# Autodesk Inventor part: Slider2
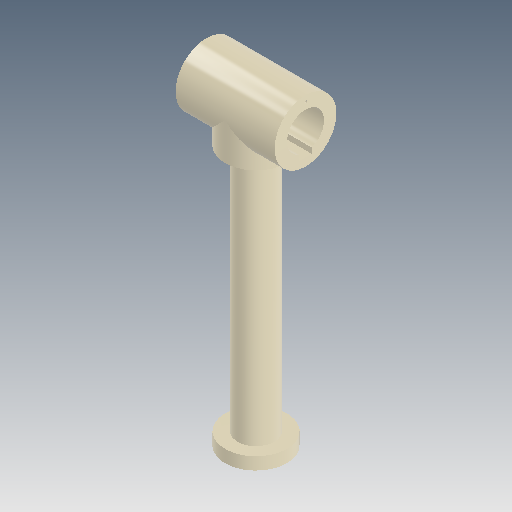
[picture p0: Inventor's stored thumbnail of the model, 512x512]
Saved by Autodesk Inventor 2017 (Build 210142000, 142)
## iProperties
Created: 2015-03
Part Number: Slider2
Document SubType Name: Modeling
Designer: Administrator
Density: 1 g/cm^3
Mass: 2.19166 g
Surface Area: 19.3417 cm^2
Volume: 2.19166 cm^3
Material: Generic
Appearance: Light Beige
Author: Administrator
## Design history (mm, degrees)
sketch "Sketch1"
  geometry: L1 (-4.037, 0)-(-4.037, 3); L2 (-4.037, 3)-(-20.037, 3); L3 (-59.037, 0)-(-4.037, 0); L4 (-20.037, 3)-(-20.037, 5); L5 (-20.037, 5)-(-4.037, 5); L6 (-4.037, 5)-(-4.037, 3); L7 (0, 0)-(-4.037, 0)
  constraints: 14 end point, 4 perpendicular, 2 parallel, 1 vertical, 1 other
  dimensions: "d0" = 3 distance of L1.start L1.end; "d3" = 16 distance of L1.end L2.end; "d5" = 2 distance between parallel lines of L5 L2
revolve "Revolution2" sketch "Sketch1" stored, may be unused: angle "d6" = 90 deg
sketch "Sketch2"
  geometry: L1 (-20.037, -5)-(-20.037, 5) reference; L2 (-4.037, -5)-(-4.037, 5) reference; L3 (-20.037, 0)-(-4.037, 0); L4 (-12.037, 0)-(-12.037, -40.229); L5 (-12.037, 0)-(-12.037, -66.218); L6 (-12.037, -3)-(-9.037, -3); L7 (-9.037, -3)-(-9.037, -4); L8 (-9.037, -4)-(-12.037, -4); L9 (-9.037, -4)-(-7.037, -4); L10 (-7.037, -4)-(-7.037, -6); L11 (-7.037, -6)-(-9.051, -6); L12 (-9.051, -6)-(-9.051, -46); L13 (-9.051, -46)-(-7.051, -46); L14 (-7.051, -46)-(-7.051, -48); L15 (-7.051, -48)-(-8.94, -48); L16 (-8.94, -48)-(-12.037, -48); L17 (-12.037, -3)-(-12.037, -48)
  constraints: 30 end point, 6 perpendicular, 5 parallel, 3 midpoint, 3 point on line, 2 collinear
  dimensions: "d7" = 0 distance between parallel lines of L4 L5; "d8" = 3 distance from line of L4.start L6; "d9" = 3 distance between parallel lines of L5 L7; "d10" = 1 distance between parallel lines of L6 L8; "d11" = 2 distance between parallel lines of L9 L11; "d12" = 2 distance from line of L13 L15.end; "d13" = 40 distance between parallel lines of L13 L11; "d14" = 2 distance between parallel lines of L7 L10; "d15" = 2 distance between parallel lines of L12 L14
revolve "Revolution3" sketch "Sketch2" stored, may be unused: angle "d16" = 90 deg
sketch "Sketch3"
  geometry: C1 r 5 at (0, 0) reference; C2 r 0.25 at (0, 4)
  constraints: 1 centre point
  dimensions: "d17" = 0.5 diameter of C2; "d18" = 4 distance of C2.centre C1.centre
extrude "Extrusion1" cut sketch "Sketch3" stored distance "d19" = 10; taper "d20" = 0 deg
sketch "Sketch5"
  geometry: L1 (-4, -3)-(4, -3) reference; L2 (4, 3)-(-4, 3) reference; A1 r 5 centre (0, 0) between (-4, -3) and (4, -3) reference; A2 r 5 centre (0, 0) between (4, 3) and (-4, 3) reference
extrude "Extrusion3" join sketch "Sketch5" stored distance "d23" = 10; taper "d24" = 0 deg
sketch "Sketch6"
  geometry: L1 (1, -3.7)-(-1, -3.7); L2 (-1, -3.7)-(-1, -1.7); L3 (-1, -1.7)-(1, -1.7); L4 (1, -1.7)-(1, -3.7); C1 r 0.25 at (0, 4) reference; C2 r 3 at (0, 0) reference; C3 r 5 at (0, 0) reference; 1 further point
  constraints: 8 end point, 2 parallel, 1 horizontal, 1 perpendicular
  dimensions: "d25" = 2 distance of L2.end L3.end; "d26" = 1 distance from line of L2 C2.centre; "d27" = 3.7 distance from line of L1 C2.centre; "d28" = 2 distance of L3.end L1.start
extrude "Extrusion4" cut sketch "Sketch6" stored distance "d29" = 10; taper "d30" = 0 deg
body "Solid1"
node "Projected Loop1"
node "Projected Loop2"
